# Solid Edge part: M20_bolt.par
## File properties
Title: Hex head screw, M20-2.5 x 45 - NAAMS F052015
Author: TraceParts S.A.
Template: Iso Metric Part.par
Last saved by: Nimesh.N
Revision: 7
Application: TraceParts
Company: TraceParts S.A.
Density: 7833.000 kg/m^3
Accuracy: 0.990
NOTE: Color blue per NAAMS assembly Standards page F-2, Section B, Paragraph 9.
REFERENCE: F052015
MATERIAL: Class10.9
STANDARD: NAAMS F05
DESIGN: Hex head screw, M20-2.5 x 45 - NAAMS F052015
OMNICLASS23: 23.13.23.11.13.21
TraceParts.PartStatus: Published
TraceParts.PartNumber: 10-11082003-104162
TraceParts.InstanceId: 10-11082003-104162C76GZXYF01FNAD6E73D4KRC2H
TraceParts.PartLanguage: en
TraceParts.PartTitle: Hex head screw NAAMS F05 SERIES
TraceParts.PartVersion: 1.3.0
TRACEPARTS: TRACEPARTS
TraceParts.ClassPath: NAAMS:10-11082003-104162
TraceParts.PartStandardAcronym: NAAMS
Username: Nimesh.N
Material: Steel
Face Style: Steel
Fill Style: ANSI32(Steel)
Virtual Style: Machined steel
Grouping: Metals\Steel
LibraryName: Materials
Coef. of Thermal Exp: 1.3e-05
Thermal Conductivity: 32.0
Specific Heat: 481.0
Modulus of Elasticity: 199947953000.0
Poisson's Ratio: 0.29
Yield Stress: 262000766.0
Ultimate Stress: 358527364.0
Elongation: 0.0
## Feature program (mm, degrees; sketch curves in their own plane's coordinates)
body "unnamed Body 1"
thread "unnamed Thread 1"
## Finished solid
Body 1: solid body, 21 faces, 37 edges, 25 vertices.
  Faces by surface: plane 10, cone 8, cylinder 2, torus 1
  Edges by curve: circle 13, line 12, spline 12
Bounding box of the edges (mm; curved faces can reach further): 30.000 x 34.641 x 57.880, from (-15, -17.3205, -12.88) to (15, 17.3205, 45).
Cylindrical faces by radius (mm): R10 x1, R13.85 x1
Conical faces (half-angle, radius in mm at the cone's reference point): 45 deg R9.3234 x1, 60 deg R16.1625 x6, 81.4164 deg R12.525 x1
Toroidal faces (ring radius, tube radius in mm): R10.8 r0.8 x1
Planar faces by outward normal: +x 1, +z 3, -x 1, -z 1, oblique 4
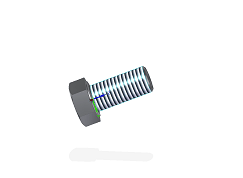
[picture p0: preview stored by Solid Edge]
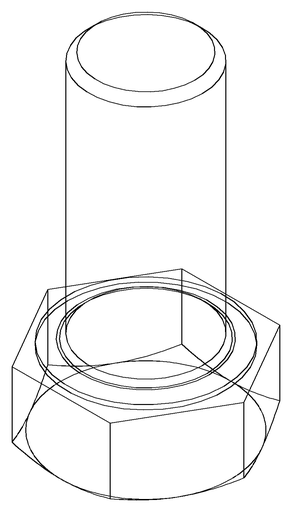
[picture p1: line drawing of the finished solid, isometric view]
